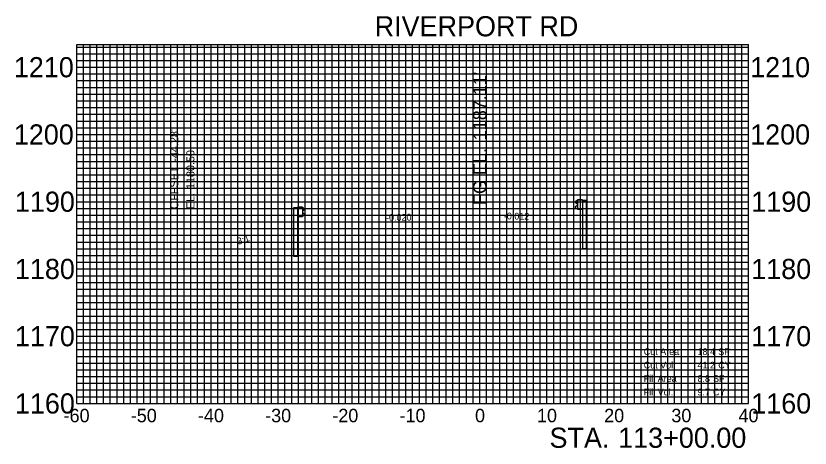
# Model space of a CAD drawing. Extents: x -69 to 49, y 1153 to 1218.
import ezdxf

# ---------------------------------------------------------------- set-up
doc = ezdxf.new("R2010")
doc.units = 0
for name, color, linetype in [('DES - SHEET - Light Grid', 7, 'Continuous'), ('DES - SHEET - Linework', 7, 'Continuous'), ('DES - XS - Proposed - Finished Grade Slopes Text', 7, 'Continuous'), ('DES - XS - Proposed - Text', 7, 'Continuous'), ('SUR - DTM - Breaklines', 7, 'Continuous')]:
    doc.layers.add(name, color=color, linetype=linetype)

msp = doc.modelspace()

# ---------------------------------------------------------------- linework, layer by layer
at = {"layer": 'DES - SHEET - Light Grid'}
for p, q in [((-60, 1213), (40, 1213)), ((-59, 1160), (-59, 1213.39)), ((-58, 1160), (-58, 1213.39)), ((-57, 1160), (-57, 1213.39)), ((-56, 1160), (-56, 1213.39)), ((-55, 1160), (-55, 1213.39)), ((-54, 1160), (-54, 1213.39)), ((-53, 1160), (-53, 1213.39)), ((-52, 1160), (-52, 1213.39)), ((-51, 1160), (-51, 1213.39)), ((-49, 1160), (-49, 1213.39)), ((-48, 1160), (-48, 1213.39)), ((-47, 1160), (-47, 1213.39)), ((-46, 1160), (-46, 1213.39)), ((-45, 1160), (-45, 1213.39)), ((-44, 1160), (-44, 1213.39)), ((-43, 1160), (-43, 1213.39)), ((-42, 1160), (-42, 1213.39)), ((-41, 1160), (-41, 1213.39)), ((-39, 1160), (-39, 1213.39)), ((-38, 1160), (-38, 1213.39)), ((-37, 1160), (-37, 1213.39)), ((-36, 1160), (-36, 1213.39)), ((-35, 1160), (-35, 1213.39)), ((-34, 1160), (-34, 1213.39)), ((-33, 1160), (-33, 1213.39)), ((-32, 1160), (-32, 1213.39)), ((-31, 1160), (-31, 1213.39)), ((-29, 1160), (-29, 1213.39)), ((-28, 1160), (-28, 1213.39)), ((-27, 1160), (-27, 1213.39)), ((-26, 1160), (-26, 1213.39)), ((-25, 1160), (-25, 1213.39)), ((-24, 1160), (-24, 1213.39)), ((-23, 1160), (-23, 1213.39)), ((-22, 1160), (-22, 1213.39)), ((-21, 1160), (-21, 1213.39)), ((-19, 1160), (-19, 1213.39)), ((-18, 1160), (-18, 1213.39)), ((-17, 1160), (-17, 1213.39)), ((-16, 1160), (-16, 1213.39)), ((-15, 1160), (-15, 1213.39)), ((-14, 1160), (-14, 1213.39)), ((-13, 1160), (-13, 1213.39)), ((-12, 1160), (-12, 1213.39)), ((-11, 1160), (-11, 1213.39)), ((-9, 1160), (-9, 1213.39)), ((-8, 1160), (-8, 1213.39)), ((-7, 1160), (-7, 1213.39)), ((-6, 1160), (-6, 1213.39)), ((-5, 1160), (-5, 1213.39)), ((-4, 1160), (-4, 1213.39)), ((-3, 1160), (-3, 1213.39)), ((-2, 1160), (-2, 1213.39)), ((-1, 1160), (-1, 1213.39)), ((1, 1160), (1, 1213.39)), ((2, 1160), (2, 1213.39)), ((3, 1160), (3, 1213.39)), ((4, 1160), (4, 1213.39)), ((5, 1160), (5, 1213.39)), ((6, 1160), (6, 1213.39)), ((7, 1160), (7, 1213.39)), ((8, 1160), (8, 1213.39)), ((9, 1160), (9, 1213.39)), ((11, 1160), (11, 1213.39)), ((12, 1160), (12, 1213.39)), ((13, 1160), (13, 1213.39)), ((14, 1160), (14, 1213.39)), ((15, 1160), (15, 1213.39)), ((16, 1160), (16, 1213.39)), ((17, 1160), (17, 1213.39)), ((18, 1160), (18, 1213.39)), ((19, 1160), (19, 1213.39)), ((21, 1160), (21, 1213.39)), ((22, 1160), (22, 1213.39)), ((23, 1160), (23, 1213.39)), ((24, 1160), (24, 1213.39)), ((25, 1160), (25, 1213.39)), ((26, 1160), (26, 1213.39)), ((27, 1160), (27, 1213.39)), ((28, 1160), (28, 1213.39)), ((29, 1160), (29, 1213.39)), ((31, 1160), (31, 1213.39)), ((32, 1160), (32, 1213.39)), ((33, 1160), (33, 1213.39)), ((34, 1160), (34, 1213.39)), ((35, 1160), (35, 1213.39)), ((36, 1160), (36, 1213.39)), ((37, 1160), (37, 1213.39)), ((38, 1160), (38, 1213.39)), ((39, 1160), (39, 1213.39)), ((-60, 1212), (40, 1212)), ((-60, 1211), (40, 1211)), ((-60, 1209), (40, 1209)), ((-60, 1208), (40, 1208)), ((-60, 1207), (40, 1207)), ((-60, 1206), (40, 1206)), ((-60, 1205), (40, 1205)), ((-60, 1204), (40, 1204)), ((-60, 1203), (40, 1203)), ((-60, 1202), (40, 1202)), ((-60, 1201), (40, 1201)), ((-60, 1199), (40, 1199)), ((-60, 1198), (40, 1198)), ((-60, 1197), (40, 1197)), ((-60, 1196), (40, 1196)), ((-60, 1195), (40, 1195)), ((-60, 1194), (40, 1194)), ((-60, 1193), (40, 1193)), ((-60, 1192), (40, 1192)), ((-60, 1191), (40, 1191)), ((-60, 1189), (40, 1189)), ((-60, 1188), (40, 1188)), ((-60, 1187), (40, 1187)), ((-60, 1186), (40, 1186)), ((-60, 1185), (40, 1185)), ((-60, 1184), (40, 1184)), ((-60, 1183), (40, 1183)), ((-60, 1182), (40, 1182)), ((-60, 1181), (40, 1181)), ((-60, 1179), (40, 1179)), ((-60, 1178), (40, 1178)), ((-60, 1177), (40, 1177)), ((-60, 1176), (40, 1176)), ((-60, 1175), (40, 1175)), ((-60, 1174), (40, 1174)), ((-60, 1173), (40, 1173)), ((-60, 1172), (40, 1172)), ((-60, 1171), (40, 1171)), ((-60, 1169), (40, 1169)), ((-60, 1168), (40, 1168)), ((-60, 1167), (40, 1167)), ((-60, 1166), (40, 1166)), ((-60, 1165), (40, 1165)), ((-60, 1164), (40, 1164)), ((-60, 1163), (40, 1163)), ((-60, 1162), (40, 1162)), ((-60, 1161), (40, 1161))]:
    msp.add_line(p, q, dxfattribs=at)
at = {"layer": 'DES - SHEET - Linework'}
for p, q in [((-60, 1213.39), (40, 1213.39)), ((-60, 1160), (-60, 1213.39)), ((-50, 1160), (-50, 1213.39)), ((-40, 1160), (-40, 1213.39)), ((-30, 1160), (-30, 1213.39)), ((-20, 1160), (-20, 1213.39)), ((-10, 1160), (-10, 1213.39)), ((0, 1160), (0, 1213.39)), ((10, 1160), (10, 1213.39)), ((20, 1160), (20, 1213.39)), ((30, 1160), (30, 1213.39)), ((40, 1160), (40, 1213.39)), ((-60, 1210), (40, 1210)), ((-60, 1200), (40, 1200)), ((-60, 1190), (40, 1190)), ((-60, 1180), (40, 1180)), ((-60, 1170), (40, 1170)), ((-60, 1160), (40, 1160))]:
    msp.add_line(p, q, dxfattribs=at)
at = {"layer": 'SUR - DTM - Breaklines'}
for p, q in [((14.36, 1190.13), (14.23, 1190.04)), ((14.23, 1189.88), (14.48, 1189.71)), ((14.48, 1189.44), (14.23, 1189.26)), ((14.52, 1190.19), (14.48, 1190.18)), ((14.52, 1189.63), (14.52, 1189.52)), ((14.54, 1190.29), (14.54, 1190.29)), ((14.54, 1190.29), (15.29, 1190.29)), ((15.29, 1190.29), (14.54, 1190.29)), ((14.54, 1190.29), (14.54, 1188.89)), ((14.54, 1190.29), (14.54, 1188.89)), ((15.29, 1190.29), (15.29, 1190.29)), ((15.29, 1190.29), (15.29, 1188.89)), ((15.29, 1190.29), (15.29, 1188.89)), ((15.29, 1190.17), (15.29, 1190.17)), ((15.29, 1190.17), (15.3, 1190.17)), ((15.3, 1190.17), (15.29, 1190.17)), ((15.29, 1190.17), (15.29, 1182.97)), ((15.29, 1190.17), (15.29, 1182.97)), ((15.3, 1190.17), (15.3, 1190.17)), ((15.3, 1190.17), (15.85, 1190.17)), ((15.85, 1190.17), (15.3, 1190.17)), ((15.3, 1190.17), (15.3, 1190.17)), ((15.3, 1190.17), (15.3, 1182.97)), ((15.3, 1190.17), (15.3, 1182.97)), ((15.3, 1190.17), (15.3, 1182.97)), ((15.3, 1190.17), (15.3, 1182.97)), ((15.85, 1190.17), (15.85, 1190.17)), ((15.85, 1190.17), (15.87, 1190.17)), ((15.87, 1190.17), (15.85, 1190.17)), ((15.85, 1190.17), (15.85, 1190.17)), ((15.85, 1190.17), (15.85, 1182.97)), ((15.85, 1190.17), (15.85, 1182.97)), ((15.85, 1190.17), (15.85, 1182.97)), ((15.85, 1190.17), (15.85, 1182.97)), ((15.87, 1190.17), (15.87, 1190.17)), ((15.87, 1190.17), (15.87, 1182.97)), ((15.87, 1190.17), (15.87, 1182.97)), ((-27.71, 1189.09), (-27.73, 1189.09)), ((-27.73, 1189.09), (-27.73, 1189.09)), ((-27.73, 1189.09), (-27.71, 1189.09)), ((-27.73, 1189.09), (-27.73, 1181.89)), ((-27.73, 1189.09), (-27.73, 1181.89)), ((-27.16, 1189.09), (-27.71, 1189.09)), ((-27.71, 1189.09), (-27.71, 1189.09)), ((-27.71, 1189.09), (-27.71, 1189.09)), ((-27.71, 1189.09), (-27.16, 1189.09)), ((-27.71, 1189.09), (-27.71, 1181.89)), ((-27.71, 1189.09), (-27.71, 1181.89)), ((-27.71, 1189.09), (-27.71, 1181.89)), ((-27.71, 1189.09), (-27.71, 1181.89)), ((-27.14, 1189.09), (-27.16, 1189.09)), ((-27.16, 1189.09), (-27.16, 1189.09)), ((-27.16, 1189.09), (-27.16, 1189.09)), ((-27.16, 1189.09), (-27.14, 1189.09)), ((-27.16, 1189.09), (-27.16, 1181.89)), ((-27.16, 1189.09), (-27.16, 1181.89)), ((-27.16, 1189.09), (-27.16, 1181.89)), ((-27.16, 1189.09), (-27.16, 1181.89)), ((-26.39, 1189.2), (-27.14, 1189.2)), ((-27.14, 1189.2), (-27.14, 1189.2)), ((-27.14, 1189.2), (-26.39, 1189.2)), ((-27.14, 1189.2), (-27.14, 1187.8)), ((-27.14, 1189.2), (-27.14, 1187.8)), ((-27.14, 1189.09), (-27.14, 1189.09)), ((-27.14, 1189.09), (-27.14, 1181.89)), ((-27.14, 1189.09), (-27.14, 1181.89)), ((-26.39, 1189.2), (-26.39, 1189.2)), ((-26.39, 1189.2), (-26.39, 1187.8)), ((-26.39, 1189.2), (-26.39, 1187.8)), ((-26.38, 1189.1), (-26.34, 1189.09)), ((-26.38, 1188.54), (-26.38, 1188.43)), ((-26.09, 1188.8), (-26.34, 1188.62)), ((-26.34, 1188.35), (-26.09, 1188.18)), ((-26.22, 1189.04), (-26.09, 1188.95)), ((14.23, 1189.11), (14.36, 1189.02)), ((14.48, 1188.97), (14.52, 1188.96)), ((14.54, 1188.89), (14.54, 1188.89)), ((14.54, 1188.89), (15.29, 1188.89)), ((15.29, 1188.89), (14.54, 1188.89)), ((15.29, 1188.89), (15.29, 1188.89)), ((-26.39, 1187.8), (-27.14, 1187.8)), ((-27.14, 1187.8), (-27.14, 1187.8)), ((-27.14, 1187.8), (-26.39, 1187.8)), ((-26.39, 1187.8), (-26.39, 1187.8)), ((-26.34, 1187.88), (-26.38, 1187.87)), ((-26.09, 1188.02), (-26.22, 1187.93)), ((15.29, 1182.97), (15.29, 1182.97)), ((15.29, 1182.97), (15.3, 1182.97)), ((15.3, 1182.97), (15.29, 1182.97)), ((15.3, 1182.97), (15.3, 1182.97)), ((15.3, 1182.97), (15.85, 1182.97)), ((15.85, 1182.97), (15.3, 1182.97)), ((15.3, 1182.97), (15.3, 1182.97)), ((15.85, 1182.97), (15.85, 1182.97)), ((15.85, 1182.97), (15.87, 1182.97)), ((15.87, 1182.97), (15.85, 1182.97)), ((15.85, 1182.97), (15.85, 1182.97)), ((15.87, 1182.97), (15.87, 1182.97)), ((-27.71, 1181.89), (-27.73, 1181.89)), ((-27.73, 1181.89), (-27.73, 1181.89)), ((-27.73, 1181.89), (-27.71, 1181.89)), ((-27.16, 1181.89), (-27.71, 1181.89)), ((-27.71, 1181.89), (-27.71, 1181.89)), ((-27.71, 1181.89), (-27.71, 1181.89)), ((-27.71, 1181.89), (-27.16, 1181.89)), ((-27.14, 1181.89), (-27.16, 1181.89)), ((-27.16, 1181.89), (-27.16, 1181.89)), ((-27.16, 1181.89), (-27.16, 1181.89)), ((-27.16, 1181.89), (-27.14, 1181.89)), ((-27.14, 1181.89), (-27.14, 1181.89))]:
    msp.add_line(p, q, dxfattribs=at)
for centre, radius, start, end in [((14.28, 1189.96), 0.0938, 125, 235), ((14.54, 1189.88), 0.3, 100, 125), ((14.43, 1189.63), 0.0938, 0, 55), ((14.43, 1189.52), 0.0937, 305, 0), ((-26.29, 1188.54), 0.0938, 125, 180), ((-26.29, 1188.43), 0.0937, 180, 235), ((-26.39, 1188.8), 0.3, 55, 80), ((-26.14, 1188.87), 0.0938, 305, 55), ((-26.14, 1188.1), 0.0938, 305, 55), ((14.28, 1189.19), 0.0938, 125, 235), ((14.54, 1189.26), 0.3, 235, 260), ((-26.39, 1188.18), 0.3, 280, 305)]:
    msp.add_arc(centre, radius, start, end, dxfattribs=at)

# ---------------------------------------------------------------- texts
at = {"layer": 'DES - XS - Proposed - Finished Grade Slopes Text'}
for s, height, rotation, p in [("-44.28'", 1.2, 90, (-44.88, 1195.95)), ('1180.50', 1.2, 90, (-42.48, 1191.88)), ('OFFSET ', 1.2, 90, (-44.88, 1188.9)), ('EL. ', 1.2, 90, (-42.48, 1188.9)), ('-0.020', 1, 1.1458, (-13.95, 1187.13)), ('-0.012', 1, 359.308, (3.57, 1187.37)), ('3:1', 1, 18.4332, (-35.94, 1183.58))]:
    msp.add_text(s, height=height, rotation=rotation, dxfattribs=at).set_placement(p)
at = {"layer": 'DES - XS - Proposed - Text'}
for s, height, p in [('RIVERPORT RD', 3, (-15.65, 1214.59)), ('1210', 3, (-69.36, 1208.5)), ('1210', 3, (40.24, 1208.5)), ('1200', 3, (-69.36, 1198.5)), ('1200', 3, (40.24, 1198.5)), ('1190', 3, (-69.2, 1188.5)), ('1190', 3, (40.4, 1188.5)), ('1180', 3, (-69.2, 1178.5)), ('1180', 3, (40.4, 1178.5)), ('1170', 3, (-69.2, 1168.5)), ('1170', 3, (40.4, 1168.5)), ('Cut Area', 1, (24.4, 1167.2)), ('18.4', 1, (32.4, 1167.2)), (' SF', 1, (35.12, 1167.2)), ('Cut Vol.', 1, (24.4, 1165.2)), ('41.2', 1, (32.4, 1165.2)), (' CY', 1, (35.12, 1165.2)), ('Fill Area', 1, (24.4, 1163.2)), ('8.8', 1, (32.4, 1163.2)), (' SF', 1, (34.34, 1163.2)), ('Fill Vol.', 1, (24.4, 1161.2)), ('9.7', 1, (32.4, 1161.2)), (' CY', 1, (34.34, 1161.2)), ('1160', 3, (-69.2, 1158.5)), ('1160', 3, (40.4, 1158.5)), ('-60', 2, (-61.95, 1157.2)), ('-50', 2, (-51.95, 1157.2)), ('-40', 2, (-41.95, 1157.2)), ('-30', 2, (-31.95, 1157.2)), ('-20', 2, (-21.95, 1157.2)), ('-10', 2, (-11.95, 1157.2)), ('0', 2, (-0.71, 1157.2)), ('10', 2, (8.51, 1157.2)), ('20', 2, (18.51, 1157.2)), ('30', 2, (28.51, 1157.2)), ('40', 2, (38.51, 1157.2)), (' STA. ', 3, (9.26, 1153.4)), ('113+00.00', 3, (20.59, 1153.4))]:
    msp.add_text(s, height=height, dxfattribs=at).set_placement(p)
for s, p in [("1187.11'", (1, 1199.14)), ('FG EL. ', (1, 1189.51))]:
    msp.add_text(s, height=2, rotation=90, dxfattribs=at).set_placement(p)

doc.saveas('drawing.dxf')
